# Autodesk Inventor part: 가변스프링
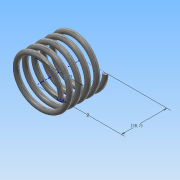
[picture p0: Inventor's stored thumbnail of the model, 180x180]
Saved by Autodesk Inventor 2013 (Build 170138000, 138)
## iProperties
Created: 2019-01
Part Number: 가변스프링
Material: 스테인리스강
Document SubType Name: Modeling
Designer: Administrator
Density: 8.08 g/cm^3
Mass: 7.81002 g
Surface Area: 19.6297 cm^2
Volume: 0.966586 cm^3
Author: Administrator
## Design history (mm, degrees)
sketch "스케치1"
  geometry: L1 (0, 0)-(10, 0); L2 (10, 0)-(10, 18.7); L3 (10, 18.7)-(0, 18.7); L4 (0, 18.7)-(0, 0); C1 r 1 at (10, 0)
  constraints: 8 end point, 2 parallel, 1 centre point, 1 coincident, 1 horizontal, 1 perpendicular
  dimensions: "d0" = 2 diameter of C1; "d1" = 20 diameter of L2 L4; "d2" = 18.7 distance between parallel lines of L1 L3 (derived)
feature "코일1" pitch "d3" = 10; turns "d5" = 5; dims "d4" = 18.7 (= d2), "d6" = 0, angle "d7" = 90 deg, angle "d8" = 90 deg, "d9" = 0, "d10" = 0
sketch "스케치2"
  geometry: L1 (-9, 0)-(-11, 0) reference; 1 further point
  constraints: 1 horizontal alignment
extrude "돌출1" cut sketch "스케치2" stored distance "d11" = 10; taper "d12" = 0 deg
node "작업 평면1"
sketch "스케치3"
  geometry: L1 (9, 0)-(11, 0) reference; 1 further point
  constraints: 1 horizontal alignment
extrude "돌출2" cut sketch "스케치3" stored distance "d13" = 10; taper "d14" = 0 deg
node "솔리드1"
node "절단 모서리 투영1"
node "절단 모서리 투영2"
